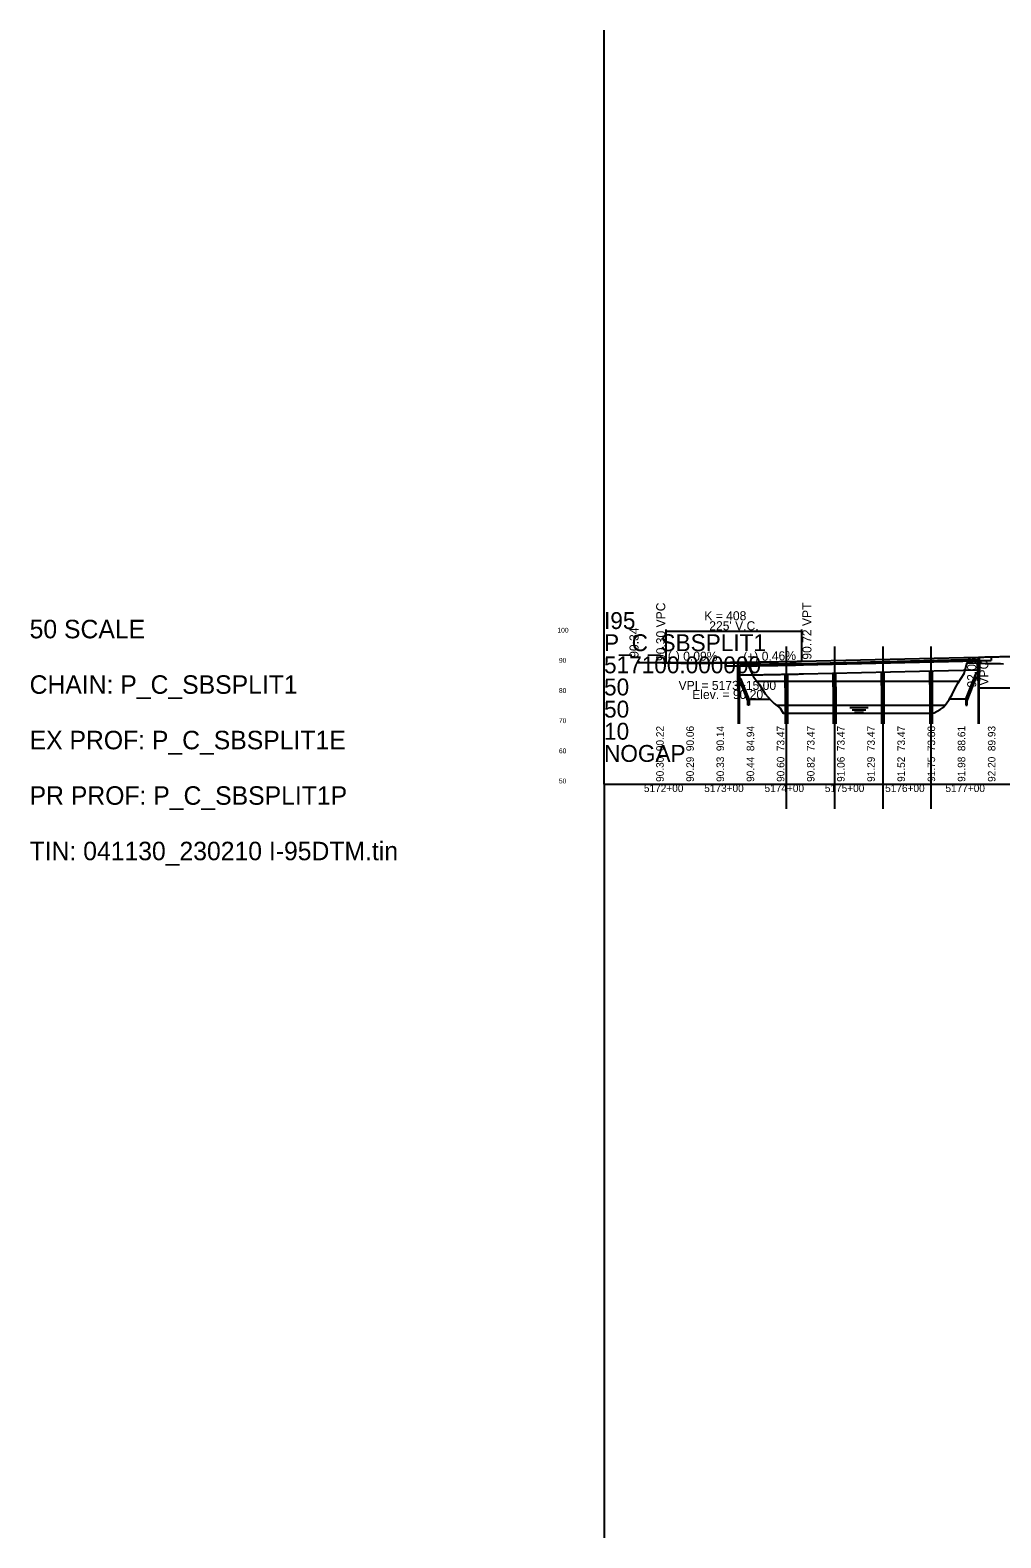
# Model space of a CAD drawing. Extents: x 2121671 to 2169879, y 557274 to 599957.
# Drawn here: x 2145716 to 2147326, y 574937 to 577437 of the extents above; entities that cross this region are included whole.
import ezdxf

# ---------------------------------------------------------------- set-up
doc = ezdxf.new("R2010")
doc.units = 0
for name, color, linetype in [('BR_CENTER LINES', 7, 'Continuous'), ('BR_CONCRETE', 7, 'Continuous'), ('BR_DETAILS', 7, 'Continuous'), ('BR_PRESTRESSED BEAM', 7, 'Continuous'), ('BR_STRUCTURAL STEEL', 7, 'Continuous'), ('RD_DDB_ElevTX', 7, 'Continuous'), ('RD_DDB_GradeTX', 7, 'Continuous'), ('RD_DDB_Profile_Elev', 7, 'Continuous'), ('RD_DDB_Profile_EX', 7, 'Continuous'), ('RD_DDB_Profile_Lbl', 7, 'Continuous'), ('RD_DDB_Profile_PR', 7, 'Continuous'), ('RD_DDB_StaTX', 7, 'Continuous'), ('RD_DDB_StripGrade', 7, 'Continuous'), ('RD_DDB_VCLbl', 7, 'Continuous'), ('RD_GPK_Profile_Cell', 7, 'Continuous'), ('RD_HC_Data_Rel', 7, 'Continuous')]:
    doc.layers.add(name, color=color, linetype=linetype)

msp = doc.modelspace()

# ---------------------------------------------------------------- linework, layer by layer
at = {"layer": 'BR_CENTER LINES'}
for p, q in [((2146970, 576414.7), (2146970, 576145.8)), ((2147050, 576414.7), (2147050, 576266.5)), ((2147050, 576414.7), (2147050, 576145.8)), ((2147130, 576414.7), (2147130, 576264.4)), ((2147130, 576414.7), (2147130, 576145.8)), ((2147210, 576414.7), (2147210, 576289.1)), ((2147210, 576414.7), (2147210, 576145.8))]:
    msp.add_line(p, q, dxfattribs=at)
at = {"layer": 'BR_CONCRETE'}
for p, q in [((2146870, 576388.5), (2146870, 576382.7)), ((2146889.3, 576382.8), (2146889.3, 576366.9)), ((2146890, 576388.7), (2146890, 576382.8)), ((2146892.8, 576366.9), (2146892.8, 576385.2)), ((2146998.8, 576386.9), (2147287.2, 576393.6)), ((2147287.2, 576375.4), (2147287.2, 576393.6)), ((2147290, 576397.2), (2147290, 576391.4)), ((2147290, 576391.4), (2147292.2, 576391.4)), ((2147290.7, 576391.4), (2147290.7, 576375.4)), ((2147310, 576397.7), (2147310, 576391.8)), ((2147208, 576351.8), (2147208, 576286.7)), ((2147212, 576351.8), (2147212, 576286.7)), ((2146968, 576346.3), (2146968, 576286.7)), ((2146972, 576346.3), (2146972, 576286.7)), ((2147048, 576348.1), (2147048, 576286.7)), ((2147052, 576348.1), (2147052, 576286.7)), ((2147128, 576349.9), (2147128, 576286.7)), ((2147132, 576349.9), (2147132, 576286.7))]:
    msp.add_line(p, q, dxfattribs=at)
for points in [[(2147287.2, 576357.9), (2147290.7, 576357.9), (2147290.7, 576375.4), (2147287.2, 576375.4)], [(2146889.3, 576349.4), (2146892.8, 576349.4), (2146892.8, 576366.9), (2146889.3, 576366.9)], [(2146967.5, 576346.3), (2146972.5, 576346.3), (2146972.5, 576366.3), (2146967.5, 576366.3)], [(2147047.5, 576348.1), (2147052.5, 576348.1), (2147052.5, 576368.1), (2147047.5, 576368.1)], [(2147127.5, 576349.9), (2147132.5, 576349.9), (2147132.5, 576369.9), (2147127.5, 576369.9)], [(2147207.5, 576351.8), (2147212.5, 576351.8), (2147212.5, 576371.8), (2147207.5, 576371.8)]]:
    msp.add_lwpolyline(points, close=True, dxfattribs=at)
for points in [[(2146870, 576382.7), (2146872.8, 576382.7), (2146877.3, 576382.7), (2146881.8, 576382.8), (2146886.3, 576382.8), (2146890, 576382.8)], [(2146892.8, 576385.2), (2146895.3, 576385.2), (2146899.8, 576385.2), (2146904.3, 576385.3), (2146908.8, 576385.3), (2146913.3, 576385.4), (2146917.8, 576385.5), (2146922.3, 576385.5), (2146926.8, 576385.6), (2146931.3, 576385.6), (2146935.8, 576385.7), (2146940.3, 576385.8), (2146944.8, 576385.9), (2146949.3, 576385.9), (2146953.8, 576386), (2146958.3, 576386.1), (2146962.8, 576386.2), (2146967.3, 576386.3), (2146971.8, 576386.3), (2146976.3, 576386.4), (2146980.8, 576386.5), (2146985.3, 576386.6), (2146989.8, 576386.7), (2146994.3, 576386.8), (2146998.8, 576386.9)], [(2147292.2, 576391.4), (2147301.2, 576391.6), (2147310, 576391.8)]]:
    msp.add_spline(points, degree=3, dxfattribs=at)
at = {"layer": 'BR_DETAILS'}
for p, q in [((2146892.8, 576361.9), (2146894.8, 576361.9)), ((2146892.8, 576354.4), (2146894.8, 576354.4)), ((2146908.6, 576327.5), (2146894.8, 576361.9)), ((2146906.6, 576325), (2146894.8, 576354.4)), ((2147268, 576327.5), (2147285.2, 576370.4)), ((2147270, 576325), (2147285.2, 576362.9)), ((2147287.2, 576370.4), (2147285.2, 576370.4)), ((2147287.2, 576362.9), (2147285.2, 576362.9)), ((2146908.6, 576327.5), (2146908.6, 576317.5)), ((2146908.6, 576327.5), (2146943.1, 576327.5)), ((2147268, 576327.5), (2147240.4, 576327.5)), ((2147268, 576327.5), (2147268, 576317.5)), ((2146906.6, 576317.5), (2146906.6, 576325)), ((2146908.6, 576317.5), (2146906.6, 576317.5)), ((2147268, 576317.5), (2147270, 576317.5)), ((2147270, 576317.5), (2147270, 576325))]:
    msp.add_line(p, q, dxfattribs=at)
for points in [[(2146968.5, 576368.8), (2146969.5, 576368.8), (2146969.5, 576366.3), (2146968.5, 576366.3)], [(2146970.5, 576368.8), (2146971.5, 576368.8), (2146971.5, 576366.3), (2146970.5, 576366.3)], [(2147048.5, 576370.6), (2147049.5, 576370.6), (2147049.5, 576368.1), (2147048.5, 576368.1)], [(2147050.5, 576370.6), (2147051.5, 576370.6), (2147051.5, 576368.1), (2147050.5, 576368.1)], [(2147128.5, 576372.4), (2147129.5, 576372.4), (2147129.5, 576369.9), (2147128.5, 576369.9)], [(2147130.5, 576372.4), (2147131.5, 576372.4), (2147131.5, 576369.9), (2147130.5, 576369.9)], [(2147208.5, 576374.3), (2147209.5, 576374.3), (2147209.5, 576371.8), (2147208.5, 576371.8)], [(2147210.5, 576374.3), (2147211.5, 576374.3), (2147211.5, 576371.8), (2147210.5, 576371.8)]]:
    msp.add_lwpolyline(points, close=True, dxfattribs=at)
at = {"layer": 'BR_PRESTRESSED BEAM'}
for p, q in [((2146998.8, 576384.4), (2147287.2, 576391.1)), ((2146998.8, 576369.4), (2147287.2, 576376.1))]:
    msp.add_line(p, q, dxfattribs=at)
for points in [[(2146892.8, 576382.7), (2146895.3, 576382.7), (2146899.8, 576382.7), (2146904.3, 576382.8), (2146908.8, 576382.8), (2146913.3, 576382.9), (2146917.8, 576383), (2146922.3, 576383), (2146926.8, 576383.1), (2146931.3, 576383.1), (2146935.8, 576383.2), (2146940.3, 576383.3), (2146944.8, 576383.4), (2146949.3, 576383.4), (2146953.8, 576383.5), (2146958.3, 576383.6), (2146962.8, 576383.7), (2146967.3, 576383.8), (2146971.8, 576383.8), (2146976.3, 576383.9), (2146980.8, 576384), (2146985.3, 576384.1), (2146989.8, 576384.2), (2146994.3, 576384.3), (2146998.8, 576384.4)], [(2146892.8, 576367.7), (2146895.3, 576367.7), (2146899.8, 576367.7), (2146904.3, 576367.8), (2146908.8, 576367.8), (2146913.3, 576367.9), (2146917.8, 576368), (2146922.3, 576368), (2146926.8, 576368.1), (2146931.3, 576368.1), (2146935.8, 576368.2), (2146940.3, 576368.3), (2146944.8, 576368.4), (2146949.3, 576368.4), (2146953.8, 576368.5), (2146958.3, 576368.6), (2146962.8, 576368.7), (2146967.3, 576368.8), (2146971.8, 576368.8), (2146976.3, 576368.9), (2146980.8, 576369), (2146985.3, 576369.1), (2146989.8, 576369.2), (2146994.3, 576369.3), (2146998.8, 576369.4)]]:
    msp.add_spline(points, degree=3, dxfattribs=at)
at = {"layer": 'BR_STRUCTURAL STEEL'}
for p, q in [((2147288.3, 576357.9), (2147288.3, 576286.7)), ((2147289.5, 576357.9), (2147289.5, 576286.7)), ((2146890.5, 576349.4), (2146890.5, 576286.7)), ((2146891.7, 576349.4), (2146891.7, 576286.7))]:
    msp.add_line(p, q, dxfattribs=at)
at = {"layer": 'RD_DDB_GradeTX'}
for p, q in [((2146820.9, 576388.1), (2146881.9, 576387.8)), ((2146944.9, 576389.3), (2146883.9, 576387.9))]:
    msp.add_line(p, q, dxfattribs=at)
for centre in [(2146725.1, 576388.5), (2146882.9, 576387.8)]:
    msp.add_circle(centre, 1, dxfattribs=at)
at = {"layer": 'RD_DDB_Profile_Elev'}
for p, q in [((2146920.9, 576357.4), (2147257, 576357.4)), ((2146954.1, 576317.4), (2147233.2, 576317.4)), ((2147075.7, 576313.7), (2147105.7, 576313.7)), ((2147079.5, 576309.9), (2147102, 576309.9)), ((2147083.2, 576306.2), (2147098.2, 576306.2))]:
    msp.add_line(p, q, dxfattribs=at)
at = {"layer": 'RD_DDB_Profile_EX'}
for points in [[(2146725.1, 576388.5), (2146730.1, 576388.5), (2146735.1, 576388.4), (2146740.1, 576388.4), (2146745.1, 576388.4), (2146750.1, 576388.3), (2146755.1, 576388.2), (2146760.1, 576388.1), (2146765.1, 576388), (2146770.1, 576387.9), (2146775.1, 576387.8), (2146780.1, 576387.7), (2146785.1, 576387.6), (2146790.1, 576387.5), (2146795.1, 576387.4), (2146800.1, 576387.2), (2146805.1, 576387.1), (2146810.1, 576387.1), (2146815.1, 576387.1), (2146820.1, 576387.2), (2146825.1, 576387.2), (2146830.1, 576387.3), (2146835.1, 576387.4), (2146840.1, 576387.4), (2146845.1, 576387.4), (2146850.1, 576387.4), (2146855.1, 576387.5), (2146860.1, 576387.5), (2146865.1, 576387.5), (2146870.1, 576387.5), (2146875.1, 576387.6), (2146880.1, 576387.6), (2146885.1, 576387.7), (2146890.1, 576387.8), (2146895.1, 576387.9), (2146900.1, 576387.9), (2146905.1, 576388), (2146910.1, 576376.3), (2146915.1, 576365.5), (2146920.1, 576358.4), (2146925.1, 576352.4), (2146930.1, 576344.5), (2146935.1, 576336.5), (2146940.1, 576330.8), (2146945.1, 576325.2), (2146950.1, 576320.5), (2146955.1, 576316.6), (2146960.1, 576312.4), (2146965.1, 576304.2), (2146970.1, 576304.2), (2146975.1, 576304.2), (2146980.1, 576304.2), (2146985.1, 576304.2), (2146990.1, 576304.2), (2146995.1, 576304.2), (2147000.1, 576304.2), (2147005.1, 576304.2), (2147010.1, 576304.2), (2147015.1, 576304.2), (2147020.1, 576304.2), (2147025.1, 576304.2), (2147030.1, 576304.2), (2147035.1, 576304.2), (2147040.1, 576304.2), (2147045.1, 576304.2), (2147050.1, 576304.2), (2147055.1, 576304.2), (2147060.1, 576304.2), (2147065.1, 576304.2), (2147070.1, 576304.2), (2147075.1, 576304.2), (2147080.1, 576304.2), (2147085.1, 576304.2), (2147090.1, 576304.2), (2147095.1, 576304.2), (2147100.1, 576304.2), (2147105.1, 576304.2), (2147110.1, 576304.2), (2147115.1, 576304.2), (2147120.1, 576304.2), (2147125.1, 576304.2), (2147130.1, 576304.2), (2147135.1, 576304.2), (2147140.1, 576304.2), (2147145.1, 576304.2), (2147150.1, 576304.2), (2147155.1, 576304.2), (2147160.1, 576304.2), (2147165.1, 576304.2), (2147170.1, 576304.2), (2147175.1, 576304.2), (2147180.1, 576304.2), (2147185.1, 576304.2), (2147190.1, 576304.2), (2147195.1, 576304.2), (2147200.1, 576304.2), (2147205.1, 576304.2), (2147210.1, 576304.2), (2147215.1, 576304.7), (2147220.1, 576307.5), (2147225.1, 576310.3)], [(2147225.1, 576310.3), (2147230.1, 576313.6), (2147235.1, 576319.8), (2147240.1, 576327), (2147245.1, 576335.4), (2147250.1, 576345.5), (2147255.1, 576354.4), (2147260.1, 576362.5), (2147265.1, 576369.8), (2147270.1, 576387.8), (2147275.1, 576387.7), (2147280.1, 576387.5), (2147285.1, 576387.3), (2147290.1, 576387.1), (2147295.1, 576387), (2147300.1, 576386.8), (2147305.1, 576386.6), (2147310.1, 576386.5), (2147315.1, 576386.5), (2147320.1, 576386.4), (2147325.1, 576386.4), (2147330.1, 576386.3)]]:
    msp.add_lwpolyline(points, dxfattribs=at)
at = {"layer": 'RD_DDB_Profile_PR'}
for p, q in [((2146725.1, 576388.5), (2146770.4, 576388.3)), ((2146995.4, 576390.4), (2147288.8, 576397.2))]:
    msp.add_line(p, q, dxfattribs=at)
for points in [[(2146770.4, 576388.3), (2146774.9, 576388.3), (2146779.4, 576388.3), (2146783.9, 576388.3), (2146788.4, 576388.3), (2146792.9, 576388.3), (2146797.4, 576388.3), (2146801.9, 576388.3), (2146806.4, 576388.2), (2146810.9, 576388.3), (2146815.4, 576388.3), (2146819.9, 576388.3), (2146824.4, 576388.3), (2146828.9, 576388.3), (2146833.4, 576388.3), (2146837.9, 576388.3), (2146842.4, 576388.3), (2146846.9, 576388.3), (2146851.4, 576388.4), (2146855.9, 576388.4), (2146860.4, 576388.4), (2146864.9, 576388.5), (2146869.4, 576388.5), (2146873.9, 576388.5), (2146878.4, 576388.6), (2146882.9, 576388.6), (2146887.4, 576388.6), (2146891.9, 576388.7), (2146896.4, 576388.7), (2146900.9, 576388.8), (2146905.4, 576388.8), (2146909.9, 576388.9), (2146914.4, 576389), (2146918.9, 576389), (2146923.4, 576389.1), (2146927.9, 576389.1), (2146932.4, 576389.2), (2146936.9, 576389.3), (2146941.4, 576389.4), (2146945.9, 576389.4), (2146950.4, 576389.5), (2146954.9, 576389.6), (2146959.4, 576389.7), (2146963.9, 576389.8), (2146968.4, 576389.9), (2146972.9, 576389.9), (2146977.4, 576390), (2146981.9, 576390.1), (2146986.4, 576390.2), (2146990.9, 576390.3), (2146995.4, 576390.4)], [(2147288.8, 576397.2), (2147297.8, 576397.4), (2147306.8, 576397.6), (2147315.8, 576397.8), (2147324.8, 576398), (2147333.8, 576398.2), (2147342.8, 576398.3), (2147351.8, 576398.5), (2147360.8, 576398.6), (2147369.8, 576398.7), (2147378.8, 576398.9), (2147387.8, 576399), (2147396.8, 576399.1), (2147405.8, 576399.2), (2147414.8, 576399.3), (2147423.8, 576399.3), (2147432.8, 576399.4), (2147441.8, 576399.5), (2147450.8, 576399.5), (2147459.8, 576399.6), (2147468.8, 576399.6), (2147477.8, 576399.6), (2147486.8, 576399.6), (2147495.8, 576399.6), (2147504.8, 576399.6), (2147513.8, 576399.6), (2147522.8, 576399.6), (2147531.8, 576399.6), (2147540.8, 576399.5), (2147549.8, 576399.5), (2147558.8, 576399.4), (2147567.8, 576399.4), (2147576.8, 576399.3), (2147585.8, 576399.2), (2147594.8, 576399.1), (2147603.8, 576399), (2147612.8, 576398.9), (2147621.8, 576398.8), (2147630.8, 576398.6), (2147639.8, 576398.5), (2147648.8, 576398.4), (2147657.8, 576398.2), (2147666.8, 576398), (2147675.8, 576397.9), (2147684.8, 576397.7), (2147693.8, 576397.5), (2147702.8, 576397.3), (2147711.8, 576397.1), (2147720.8, 576396.9), (2147729.8, 576396.6), (2147738.8, 576396.4)]]:
    msp.add_spline(points, degree=3, dxfattribs=at)
at = {"layer": 'RD_DDB_VCLbl'}
for p, q in [((2146770.4, 576442.9), (2146770.4, 576388.3)), ((2146770.4, 576440.4), (2146995.4, 576440.4)), ((2146995.4, 576442.9), (2146995.4, 576390.4)), ((2147288.8, 576343.9), (2147288.8, 576397.2)), ((2147288.8, 576346.4), (2147738.8, 576346.4))]:
    msp.add_line(p, q, dxfattribs=at)
at = {"layer": 'RD_GPK_Profile_Cell'}
for q in [(2146667.9, 577436.8), (2151167.9, 576186.8), (2146667.9, 574936.8)]:
    msp.add_line((2146667.9, 576186.8), q, dxfattribs=at)

# ---------------------------------------------------------------- texts
at = {"layer": 'RD_DDB_ElevTX'}
for s, p in [('100', (2146590.6, 576437.8)), ('90', (2146593.1, 576387.8)), ('80', (2146593.1, 576337.8)), ('70', (2146593.1, 576287.8)), ('60', (2146593.1, 576237.8)), ('50', (2146593.1, 576187.8))]:
    msp.add_text(s, height=8, dxfattribs=at).set_placement(p)
at = {"layer": 'RD_DDB_GradeTX'}
for s, rotation, p in [('(-) 0.09%', 359.7447, (2146773.5, 576391.5)), ('(+) 0.46%', 1.3258, (2146898.9, 576390.4))]:
    msp.add_text(s, height=15, rotation=rotation, dxfattribs=at).set_placement(p)
at = {"layer": 'RD_DDB_Profile_Lbl'}
msp.add_text('90.34', height=15, rotation=90, dxfattribs=at).set_placement((2146725.1, 576396.1))
for s, p in [('VPI = 5173+15.00', (2146791.5, 576342.8)), ('Elev. = 90.20', (2146814.1, 576327.8))]:
    msp.add_text(s, height=15, dxfattribs=at).set_placement(p)
at = {"layer": 'RD_DDB_StaTX'}
for s, p in [('5172+00', (2146734, 576173.5)), ('5173+00', (2146834, 576173.5)), ('5174+00', (2146934, 576173.5)), ('5175+00', (2147034, 576173.5)), ('5176+00', (2147134, 576173.5)), ('5177+00', (2147234, 576173.5))]:
    msp.add_text(s, height=12.5, dxfattribs=at).set_placement(p)
at = {"layer": 'RD_DDB_StripGrade'}
for s, height, p in [('90.30 VPC', 15, (2146769.4, 576390.7)), ('90.72 VPT', 15, (2147011.8, 576393)), ('92.08 ', 15, (2147285, 576346.7)), ('VPC', 15, (2147305.2, 576350)), ('90.22', 12.5, (2146766.9, 576241.3)), ('90.06', 12.5, (2146816.9, 576241.3)), ('90.14', 12.5, (2146866.9, 576241.3)), ('84.94', 12.5, (2146916.9, 576241.3)), ('73.47', 12.5, (2146966.9, 576241.3)), ('73.47', 12.5, (2147016.9, 576241.3)), ('73.47', 12.5, (2147066.9, 576241.3)), ('73.47', 12.5, (2147116.9, 576241.3)), ('73.47', 12.5, (2147166.9, 576241.3)), ('73.88', 12.5, (2147216.9, 576241.3)), ('88.61', 12.5, (2147266.9, 576241.3)), ('89.93', 12.5, (2147316.9, 576241.3)), ('90.30', 12.5, (2146766.9, 576190.3)), ('90.29', 12.5, (2146816.9, 576190.3)), ('90.33', 12.5, (2146866.9, 576190.3)), ('90.44', 12.5, (2146916.9, 576190.3)), ('90.60', 12.5, (2146966.9, 576190.3)), ('90.82', 12.5, (2147016.9, 576190.3)), ('91.06', 12.5, (2147066.9, 576190.3)), ('91.29', 12.5, (2147116.9, 576190.3)), ('91.52', 12.5, (2147166.9, 576190.3)), ('91.75', 12.5, (2147216.9, 576190.3)), ('91.98', 12.5, (2147266.9, 576190.3)), ('92.20', 12.5, (2147316.9, 576190.3))]:
    msp.add_text(s, height=height, rotation=90, dxfattribs=at).set_placement(p)
at = {"layer": 'RD_DDB_VCLbl'}
for s, p in [('K = 408', (2146834.2, 576458.3)), ("225' V.C.", (2146842.4, 576441.7))]:
    msp.add_text(s, height=15, dxfattribs=at).set_placement(p)
at = {"layer": 'RD_GPK_Profile_Cell'}
for s, p in [('I95', (2146667.9, 576443.8)), ('P_C_SBSPLIT1', (2146667.9, 576407.1)), ('517100.000000', (2146667.9, 576370.4)), ('50', (2146667.9, 576333.7)), ('50', (2146667.9, 576297)), ('10', (2146667.9, 576260.3)), ('NOGAP', (2146667.9, 576223.5))]:
    msp.add_text(s, height=28, dxfattribs=at).set_placement(p)
at = {"layer": 'RD_HC_Data_Rel'}
for s, height, p in [('50 SCALE', 30.67, (2145715.4, 576428.4)), ('CHAIN: P_C_SBSPLIT1', 30.668, (2145715.4, 576336.4)), ('EX PROF: P_C_SBSPLIT1E', 30.668, (2145715.4, 576244.4)), ('PR PROF: P_C_SBSPLIT1P', 30.668, (2145715.4, 576152.4)), ('TIN: 041130_230210 I-95DTM.tin', 30.668, (2145715.4, 576060.4))]:
    msp.add_text(s, height=height, rotation=360, dxfattribs=at).set_placement(p)

doc.saveas('drawing.dxf')
